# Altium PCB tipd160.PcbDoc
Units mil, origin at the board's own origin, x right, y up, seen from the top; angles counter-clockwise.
Board outline 4480.01 x 3875.01 mil, 4 copper layers (Top Layer, gnd, power, Bottom Layer), stack 90 mil thick; 78 components, 26 nets, 223 pads, 56 vias.
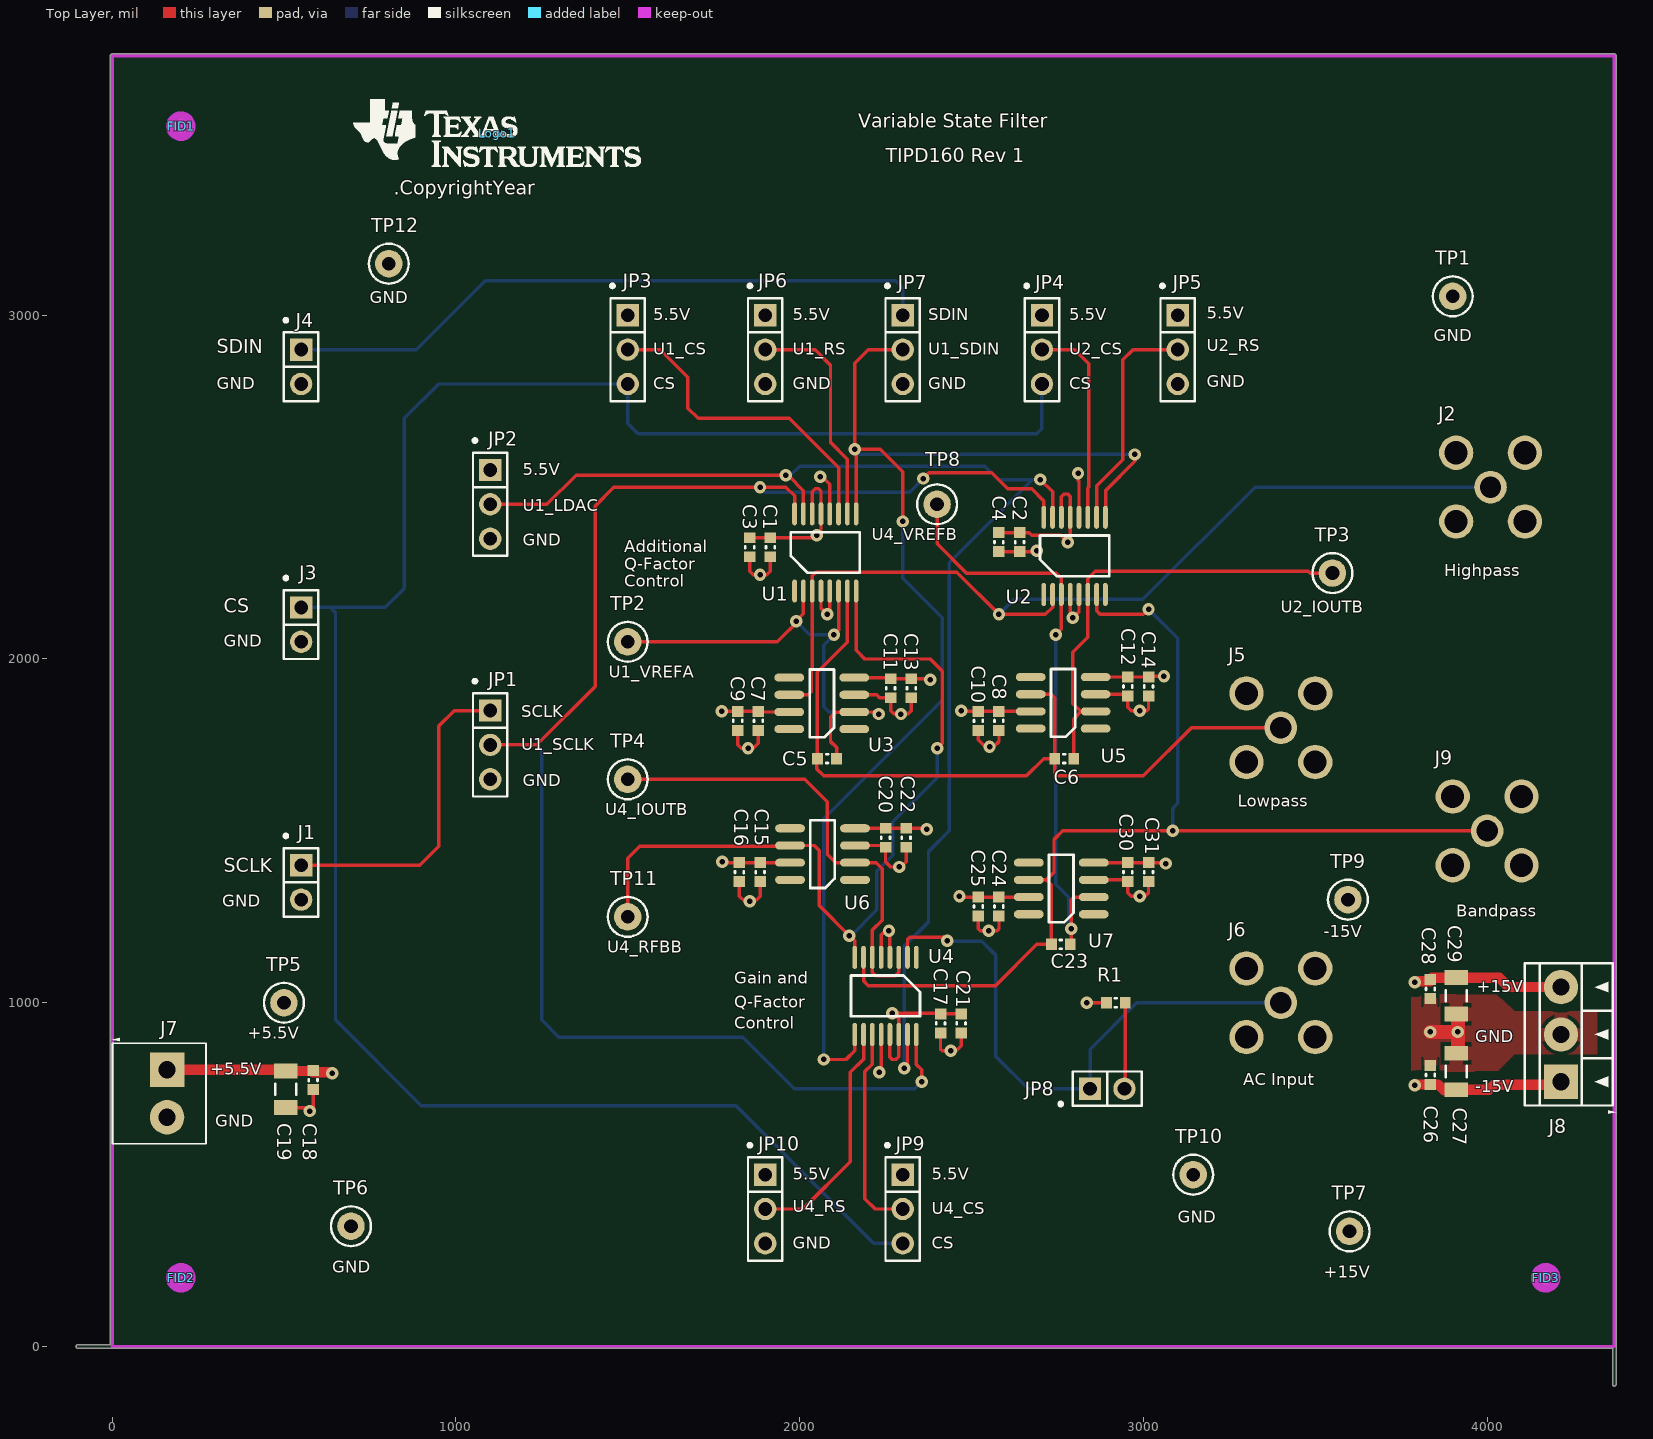
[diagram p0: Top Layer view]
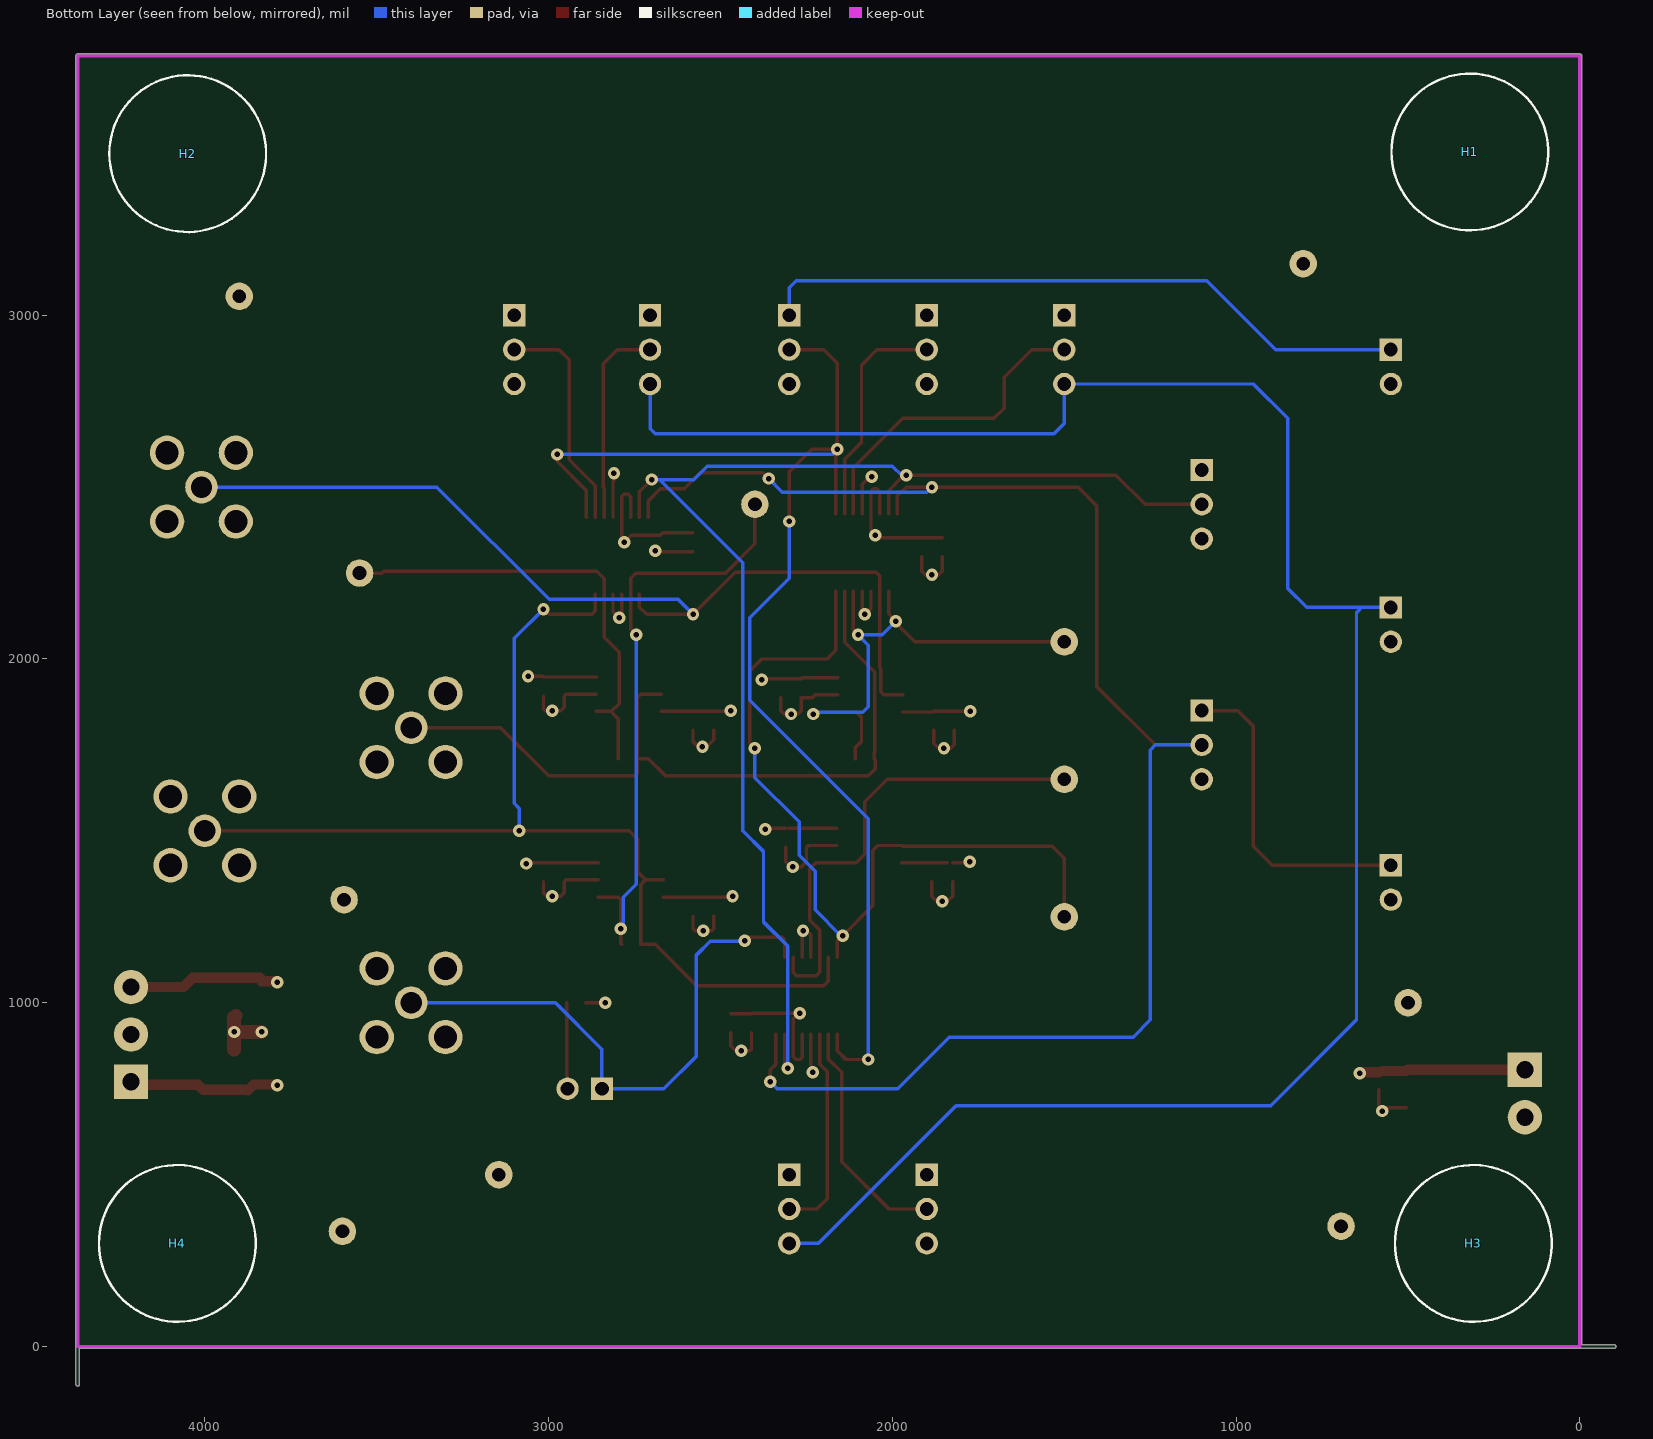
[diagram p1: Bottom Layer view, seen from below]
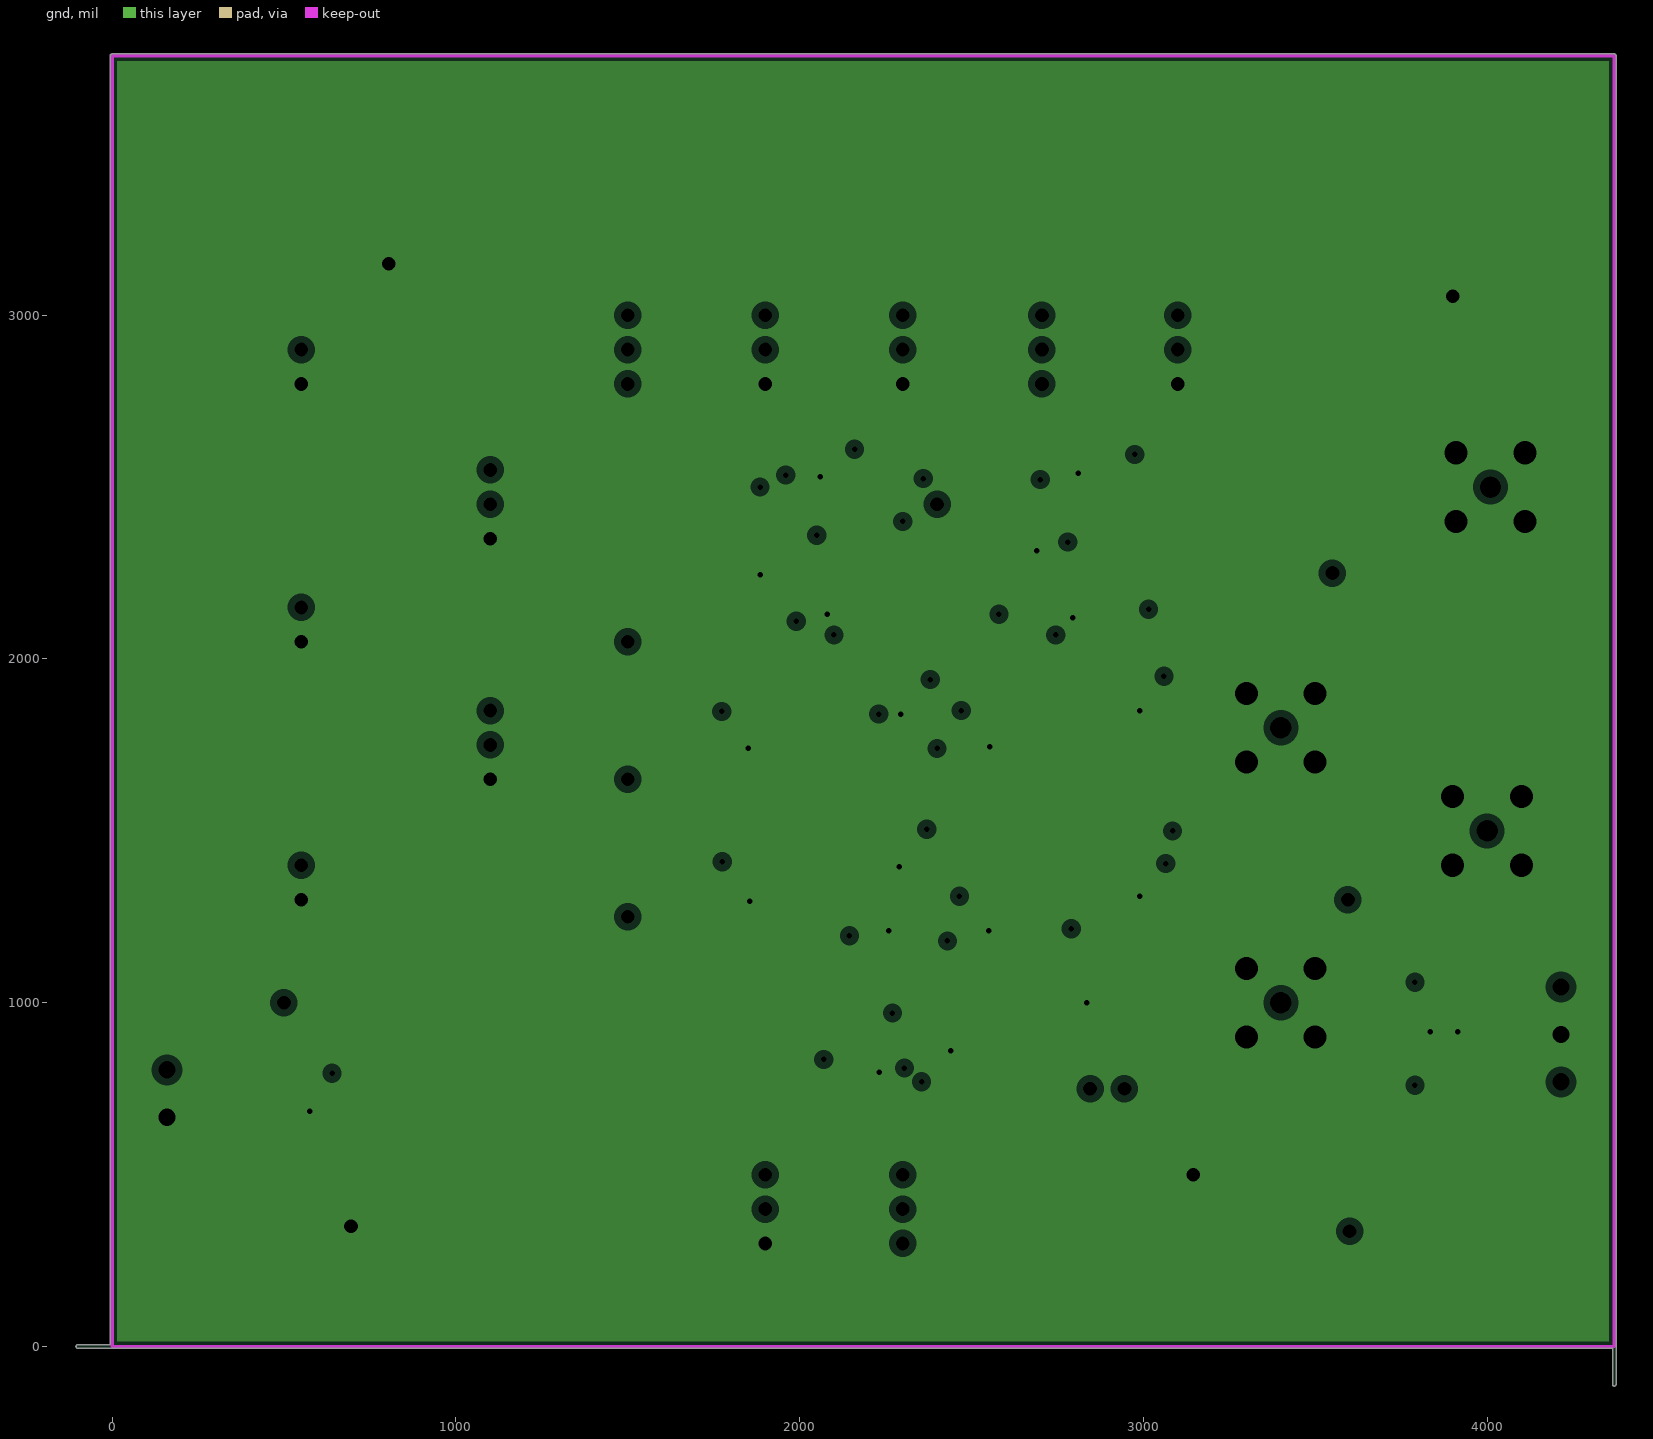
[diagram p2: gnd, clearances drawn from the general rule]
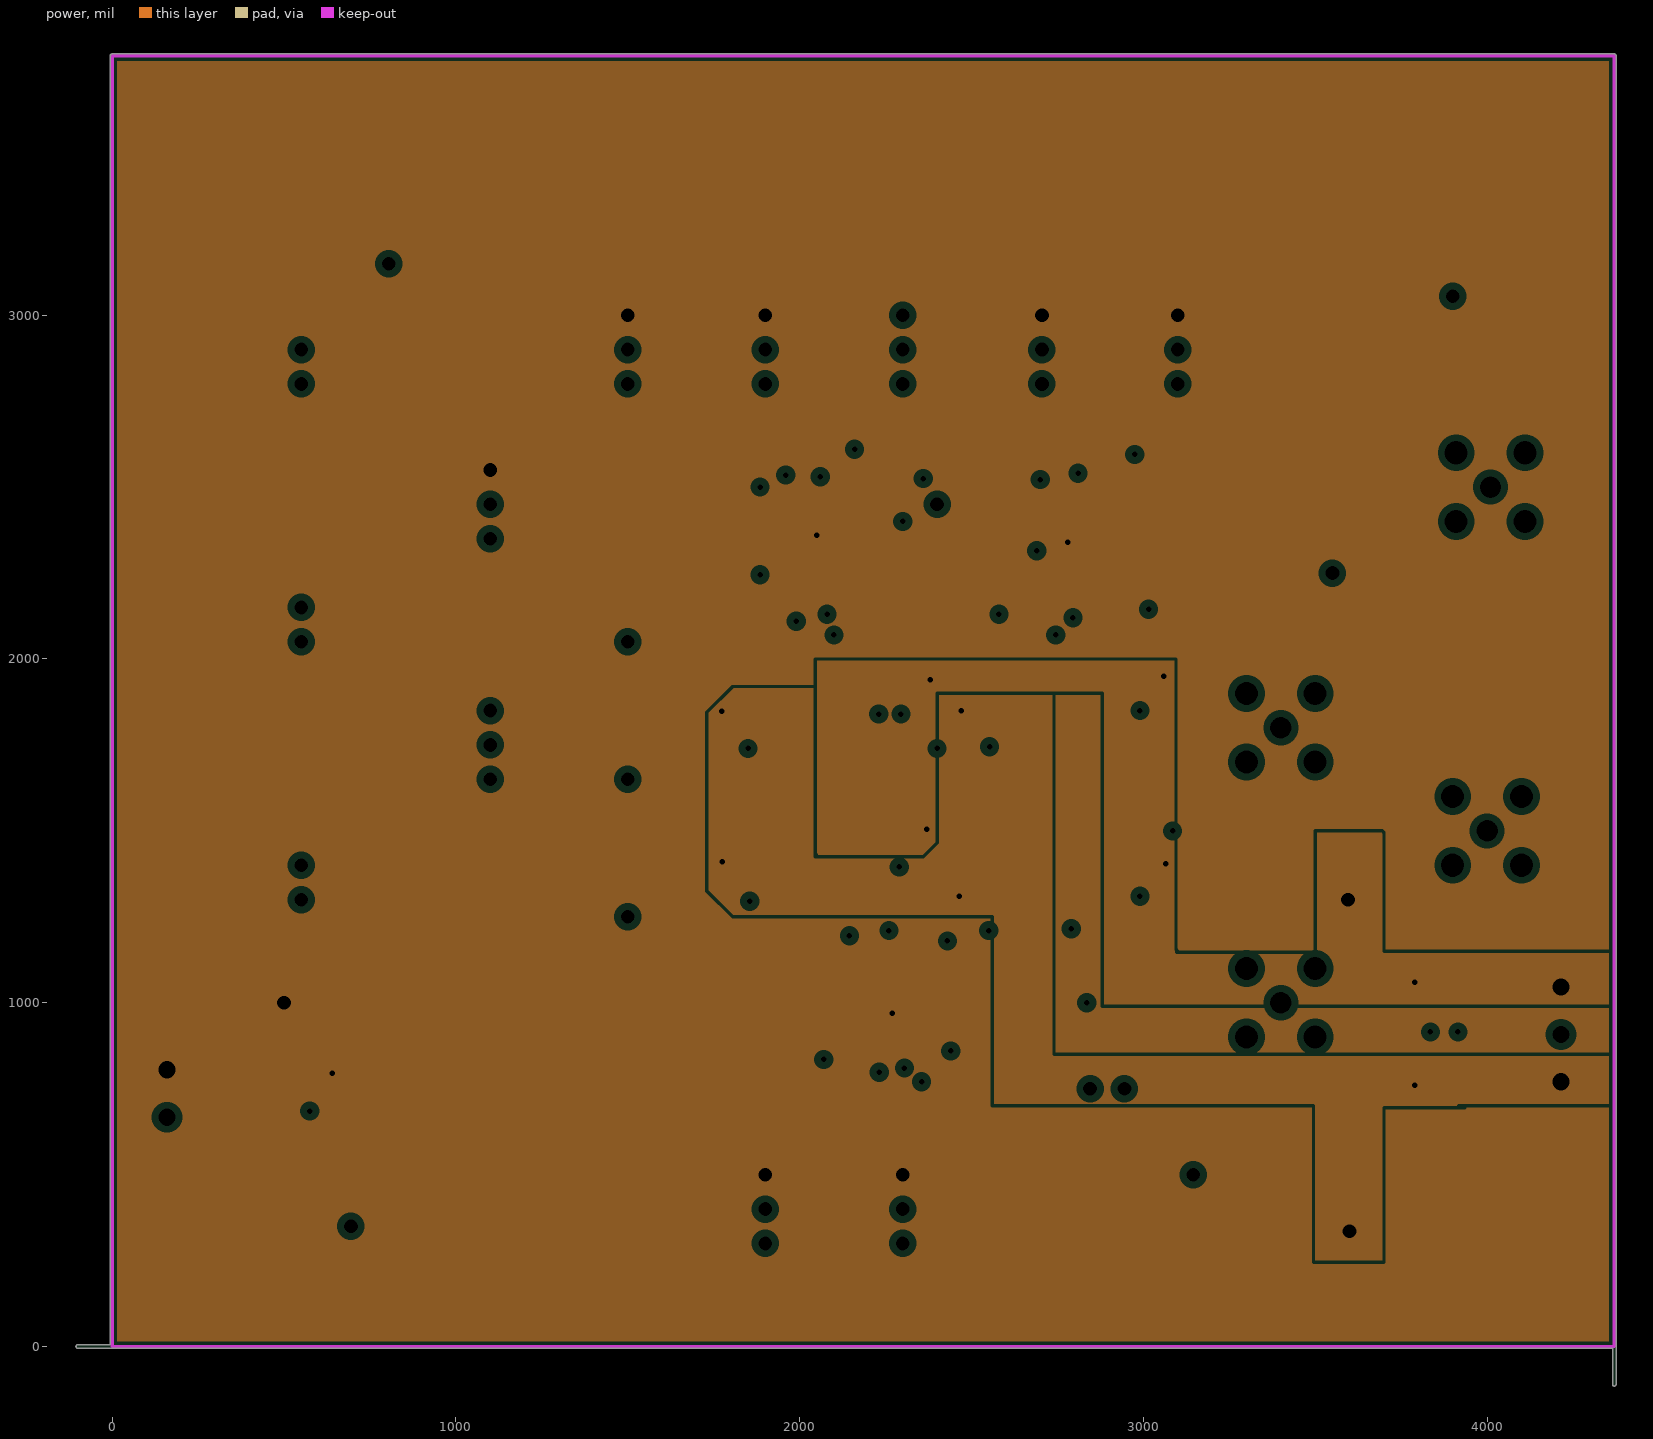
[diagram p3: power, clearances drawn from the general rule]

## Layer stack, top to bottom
Top Layer: signal copper 1.4
Dielectric: core 59.2, FR-4, Dk 4.8
gnd: plane copper 1.4, net GND
Dielectric: prepreg 12.6, FR-4, Dk 4.8
power: plane copper 1.4, net (Multiple Nets)
Dielectric: core 12.6, FR-4, Dk 4.8
Bottom Layer: signal copper 1.4

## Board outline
-100,-5.01 cw(c-100,0) -100,5.02 -5.01,5.02 -5.01,3755 cw(c0,3755) 0,3760.02 4370,3760.02 cw(c4370,3755) 4375.02,3755 4375.02,-110 cw(c4370,-110) 4364.98,-110 4364.98,-5.01

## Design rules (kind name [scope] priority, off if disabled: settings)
AcuteAngle [All] p1: minimum=4.50000000000000E+0001 checktracksonly=FALSE
AssemblyTestPointUsage [All] p1: valid=2
Clearance Clearance_BoardEdge_MountingHoles [OnCopper and InComponentClass('Mounting Holes') vs IsKeepOut] p1: gap=40
Clearance Clearance_BoardEdge_Poly [OnCopper and InPoly vs IsKeepOut] p2: gap=25
Clearance Clearance_BoardEdge [OnCopper and Not InComponentClass('Logo') and not InComponentClass('FiducialMark') and not InRegion(1000,500,4000,800) and Not IsKeepout vs IsKeepOut] p3: gap=75
Clearance Clearance_Poly [InPolygon] p4: gap=25
Clearance [All] p5: gap=8
ComponentClearance ComponentClearance_Shunt [InComponentClass('Header') vs InComponentClass('Shunt')] p1: gap=0 collisioncheckmode=3 verticalgap=0 showdistances=FALSE
ComponentClearance ComponentClearance_Logo [InComponentClass('Logo')] p2: gap=50 collisioncheckmode=3 verticalgap=10 showdistances=FALSE
ComponentClearance ComponentClearance_ScrewToNut [(HasFootprint('NY PMS 440 0025 PH')) vs (HasFootprint('Keystone_1902C'))] p3: gap=5 collisioncheckmode=3 verticalgap=10 showdistances=FALSE
ComponentClearance ComponentClearance_MountingHoles [InComponentClass('Mounting Holes')] p4: gap=250 collisioncheckmode=3 verticalgap=100000 showdistances=FALSE
ComponentClearance ComponentClearance_SmallPassives [HasFootprint('0201*') or HasFootprint('0402*') or HasFootprint('0508') or HasFootprint('0603*') or HasFootprint('0612') or HasFootprint('0805*') or HasFootprint('0815*') or HasFootprint('0830*') or HasFootprint('1206*') or HasFootprint('1210*') or HasFootprint('1808*') or HasFootprint('1812*') or HasFootprint('1825*') or HasFootprint('2010*') or HasFootprint('2220*') or HasFootprint('2225*') or HasFootprint('2512*') or HasFootprint('2728*') or HasFootprint('3518*') vs HasFootprint('0201*') or HasFootprint('0402*') or HasFootprint('0508') or HasFootprint('0603*') or HasFootprint('0612') or HasFootprint('0805*') or HasFootprint('0815*') or HasFootprint('0830*') or HasFootprint('1206*') or HasFootprint('1210*') or HasFootprint('1808*') or HasFootprint('1812*') or HasFootprint('1825*') or HasFootprint('2010*') or HasFootprint('2220*') or HasFootprint('2225*') or HasFootprint('2512*') or HasFootprint('2728*') or HasFootprint('3518*')] p5: gap=20 collisioncheckmode=3 verticalgap=10 showdistances=FALSE
ComponentClearance ComponentClearance_THtoSMT [IsThruComponent vs IsSMTComponent] p6: gap=100 collisioncheckmode=3 verticalgap=30 showdistances=FALSE
ComponentClearance ComponentClearance_THtoTH [IsThruComponent vs IsThruComponent] p7: gap=118.11 collisioncheckmode=3 verticalgap=30 showdistances=FALSE
ComponentClearance [All] p8: gap=40 collisioncheckmode=3 verticalgap=10 showdistances=FALSE
DiffPairsRouting [All] p1: maxlimit=100 minlimit=10 mostfreqgap=10 maxuncoupledlength=1000
FabricationTestPointUsage TestPointUsage [All] p1: valid=2 allowmultiple=FALSE
FabricationTestpoint Testpoint [All] p1: side=3 testpointundercomponent=TRUE minsize=40 maxsize=100 preferedsize=60 minholesize=0 maxholesize=40 preferedholesize=32 testpointgrid=1 allowsidetop=TRUE allowsidebottom=TRUE usegrid=TRUE gridtolerance=0.01
FanoutControl Fanout_LCC [IsLCC] p1: bgadir=Out bgaviamode=Centered fanoutstyle=Auto fanoutdirection=Alternating viagrid=1 // Fanout_LCC (Default Rule)
FanoutControl Fanout_BGA [IsBGA] p2: bgadir=Out bgaviamode=Centered fanoutstyle=Auto fanoutdirection=Alternating viagrid=1 // Fanout_BGA (Default Rule)
FanoutControl Fanout_Default [All] p4: bgadir=Out bgaviamode=Centered fanoutstyle=Auto fanoutdirection=Alternating viagrid=1 // Fanout_Default (Default Rule)
FanoutControl Fanout_Small [(CompPinCount < 5)] p5: bgadir=Out bgaviamode=Centered fanoutstyle=Auto fanoutdirection=OutThenIn viagrid=1 // Fanout_Small (Default Rule)
HoleSize [All] p1: absolutevalues=TRUE maxlimit=251 minlimit=8 maxpercent=80.000 minpercent=20.000
MinimumAnnularRing MinimumAnnularRing_ThermalPadVias [IsVia and InAnyComponent] p1: minimumring=5.91
MinimumAnnularRing [All] p2: minimumring=9
MinimumSolderMaskSliver MinimumSolderMaskSliver_Logo [InComponentClass('Logo') vs InComponentClass('Logo')] p1: minsoldermaskwidth=0.7
MinimumSolderMaskSliver [All] p2: minsoldermaskwidth=3.94
PlaneClearance [All] p1: clearance=20
PlaneConnect [All] p1: planeconnectstyle=Relief reliefexpansion=10 reliefentries=4 reliefconductorwidth=10 reliefairgap=10
PolygonConnect PolygonConnect_3 [All vs IsNamedPolygon('Top Layer-No Net')] p1: connectstyle=Relief reliefconductorwidth=40 reliefentries=4 polygonreliefangle="90 Angle" airgapwidth=10
PolygonConnect PolygonConnect_2 [(InNet('AGND') AND InPadClass('All Pads')) vs IsNamedPolygon('Top Layer-No Net')] p2: connectstyle=Relief reliefconductorwidth=10 reliefentries=4 polygonreliefangle="90 Angle" airgapwidth=10
PolygonConnect PolygonConnect_1 [All vs IsNamedPolygon('Top Layer-No Net')] p3: connectstyle=Relief reliefconductorwidth=40 reliefentries=4 polygonreliefangle="90 Angle" airgapwidth=10
PolygonConnect [All] p4: connectstyle=Relief reliefconductorwidth=10 reliefentries=4 polygonreliefangle="90 Angle" airgapwidth=10
RoutingVias ThermalPadVias [IsVia and InAnyComponent] p1: holewidth=7.87 width=19.68 viastyle="Through Hole" minholewidth=7.87 minwidth=19.68 maxholewidth=12.99 maxwidth=23.62
RoutingVias [All] p2: holewidth=16 width=34 viastyle="Through Hole" minholewidth=7.87 minwidth=26 maxholewidth=40 maxwidth=65
SMDToCorner [All] p1: distance=30000
SilkToSilkClearance [All] p1: silktosilkclearance=5
SilkscreenOverComponentPads [All] p1: minsilkscreentomaskgap=5
SolderMaskExpansion [All] p1: expansion=1.97
Width [All] p1: maxlimit=100 minlimit=6 preferedwidth=10 checkconnectedcopper=TRUE
13 further rules are at their usual default settings.

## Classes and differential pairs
component class Logo: Logo1
component class tipd160_hw: FID1 FID2 FID3 H1 H2 H3 H4 Logo1
component class FiducialMark: FID1 FID2 FID3
component class TIPD160: C1 C2 C3 C4 C5 C6 C7 C8 C9 C10 C11 C12 C13 C14 C16 C17 C19 C20 C21 C22 C23 C24 C25 C29 C30 C31 J1 J2 J3 J4 J5 J6 J7 J8 J9 JP1 JP2 JP3 JP4 JP5 JP6 JP7 JP8 JP9 JP10 R1 TP1 TP2 TP3 TP4 TP5 TP6 TP7 TP8 TP9 TP10 TP11 TP12 U1 U2 U3 U4 U5 U6 U7
component class Header: J1 J3 J4 JP1 JP2 JP3 JP4 JP5 JP6 JP7 JP8 JP9 JP10

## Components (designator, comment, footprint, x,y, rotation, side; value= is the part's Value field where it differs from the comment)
C1 "GRM188R61E104KA01D" 0603L 1915,2325 r270 top
C2 "GRM188R61E104KA01D" 0603L 2640,2340 r90 top
C3 "C1608C0G1H101J" 0603L 1855,2325 r270 top
C4 "C1608C0G1H101J" 0603L 2580,2340 r90 top
C5 "" 0603L 2080,1710 r180 top
C6 "GRM188R71H102KA01D" 0603L 2770,1710 r180 top
C7 "C1608C0G1H101J" 0603L 1880,1820 r90 top (schematic designator C15)
C8 "C1608C0G1H101J" 0603L 2580,1820 r270 top (schematic designator C18)
C9 "GRM188R61E104KA01D" 0603L 1820,1820 r90 top
C10 "GRM188R61E104KA01D" 0603L 2520,1820 r270 top
C11 "GRM188R61E104KA01D" 0603L 2265,1915 r90 top
C12 "GRM188R61E104KA01D" 0603L 2955,1920 r90 top
C13 "C1608C0G1H101J" 0603L 2325,1915 r90 top (schematic designator C26)
C14 "C1608C0G1H101J" 0603L 3015,1920 r90 top (schematic designator C27)
C15 "GRM188R61E104KA01D" 0603L 1885,1380 r90 top
C16 "C1608C0G1H101J" 0603L 1825,1380 r90 top (schematic designator C28)
C17 "GRM188R61E104KA01D" 0603L 2410,940 r90 top
C18 "GRM188R61E104KA01D" 0603L 585,775 r90 top
C19 "GRM31CR61E106KA12L" 1206L 505,748.15 r90 top
C20 "GRM188R61E104KA01D" 0603L 2250,1480 r90 top
C21 "C1608C0G1H101J" 0603L 2470,940 r90 top
C22 "C1608C0G1H101J" 0603L 2310,1480 r90 top
C23 "GRM188R71H102KA01D" 0603L 2760,1170 r0 top
C24 "C1608C0G1H101J" 0603L 2580,1280 r90 top
C25 "GRM188R61E104KA01D" 0603L 2520,1280 r90 top
C26 "GRM188R61E104KA01D" 0603L 3835,790 r270 top
C27 "GRM31CR61E106KA12L" 1206L 3910,800 r270 top
C28 "GRM188R61E104KA01D" 0603L 3835,1040 r270 top
C29 "GRM31CR61E106KA12L" 1206L 3910,1020 r270 top
C30 "GRM188R61E104KA01D" 0603L 2955,1380 r90 top
C31 "C1608C0G1H101J" 0603L 3015,1380 r90 top
FID1 "Fiducial" Fiducial10-20 200,3550 r0 top
FID2 "Fiducial" Fiducial10-20 200,200 r0 top
FID3 "Fiducial" Fiducial10-20 4170,200 r0 top
H1 "SJ-5303 (CLEAR)" Bumpon_SJ5003Transparent 320,3475 r270 bottom
H2 "SJ-5303 (CLEAR)" Bumpon_SJ5003Transparent 4050,3470 r180 bottom
H3 "SJ-5303 (CLEAR)" Bumpon_SJ5003Transparent 310,300 r180 bottom
H4 "SJ-5303 (CLEAR)" Bumpon_SJ5003Transparent 4080,300 r180 bottom
J1 "TSW-102-07-G-S" TSW-102-07-G-S 550,1350 r270 top
J2 "142-0701-201" Johnson_142-0701-20x 4010,2500 r0 top
J3 "TSW-102-07-G-S" TSW-102-07-G-S 550,2100 r270 top
J4 "TSW-102-07-G-S" TSW-102-07-G-S 550,2850 r270 top
J5 "142-0701-201" Johnson_142-0701-20x 3400,1800 r0 top
J6 "142-0701-201" Johnson_142-0701-20x 3400,1000 r0 top
J7 "ED555/2DS" TERM_BLK_ED555-2DS 160,805 r270 top
J8 "ED555/3DS" TERM_BLK_ED555-3DS 4215,770 r90 top
J9 "142-0701-201" Johnson_142-0701-20x 4000,1500 r0 top
JP1 "TSW-103-07-G-S" TSW-103-07-G-S 1100,1750 r270 top
JP2 "TSW-103-07-G-S" TSW-103-07-G-S 1100,2450 r270 top
JP3 "TSW-103-07-G-S" TSW-103-07-G-S 1500,2900 r270 top
JP4 "TSW-103-07-G-S" TSW-103-07-G-S 2705,2900 r270 top
JP5 "TSW-103-07-G-S" TSW-103-07-G-S 3100,2900 r270 top
JP6 "TSW-103-07-G-S" TSW-103-07-G-S 1900,2900 r270 top
JP7 "TSW-103-07-G-S" TSW-103-07-G-S 2300,2900 r270 top
JP8 "TSW-102-07-G-S" TSW-102-07-G-S 2895,750 r0 top
JP9 "TSW-103-07-G-S" TSW-103-07-G-S 2300,400 r270 top
JP10 "TSW-103-07-G-S" TSW-103-07-G-S 1900,400 r270 top
Logo1 "Texas Instruments" TI_Stacked_Overlay_Small 1120,3530 r0 top
R1 "RC0603FR-0749R9L" 0603L 2920,1000 r0 top
TP1 "5001" Keystone5001 3900,3055 r0 top
TP2 "5000" Keystone5000 1500,2050 r0 top
TP3 "5000" Keystone5000 3550,2250 r0 top
TP4 "5000" Keystone5000 1500,1650 r0 top
TP5 "5000" Keystone5000 500,1000 r90 top
TP6 "5001" Keystone5001 695,350 r0 top
TP7 "5000" Keystone5000 3600,335 r90 top
TP8 "5000" Keystone5000 2400,2450 r0 top
TP9 "5000" Keystone5000 3595,1300 r90 top
TP10 "5001" Keystone5001 3145,500 r0 top
TP11 "5000" Keystone5000 1500,1250 r0 top
TP12 "5001" Keystone5001 805,3150 r0 top
U1 "DAC8812ICPW" PW0016A_N 2075,2310 r90 top
U2 "DAC8812ICPW" PW0016A_N 2800,2300 r90 top
U3 "OPA277U" D0008A_N 2064.57,1870.87 r180 top
U4 "DAC8812ICPW" PW0016A_N 2250,1020 r270 top
U5 "OPA277U" D0008A_N 2766.69,1872.48 r180 top
U6 "OPA277U" D0008A_N 2066.69,1432.48 r180 top
U7 "OPA277U" D0008A_N 2761.26,1332.48 r180 top

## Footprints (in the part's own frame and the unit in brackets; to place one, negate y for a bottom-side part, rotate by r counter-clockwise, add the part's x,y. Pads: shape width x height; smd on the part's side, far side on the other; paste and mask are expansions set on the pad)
0603L [mm] "0603 from SM-752 data"
  rect 0.8x0.85 smd: 1(-0.7,0) 2(0.7,0)
  silkscreen extent -0.07,-0.33 0.07,0.33, body extent -0.87,-0.47 0.87,0.47, height 0.85
1206L [mm] "1206 from SM-752 data"
  rect 1.1x1.75 smd: 1(-1.35,0) 2(1.35,0)
  silkscreen extent -0.4,-0.77 0.4,0.77, body extent -1.7,-0.9 1.7,0.9, height 1.35
Bumpon_SJ5003Transparent [mil] "3M Hemispherical Bumpon transparent"
  round 1 on Mech4: 0(0,0)
  silkscreen extent -228,-228 228,228, body extent -217,-218 219,218, height 197
D0008A_N [mm] "SOIC, 8-Leads, Body 4.9x3.9mm, Pitch 1.27mm, IPC Medium Density"
  oval 2.2x0.6 smd: 1(-2.4,1.905) 2(-2.4,0.635) 3(-2.4,-0.635) 4(-2.4,-1.905) 5(2.4,-1.905) 6(2.4,-0.635) 7(2.4,0.635) 8(2.4,1.905)
  silkscreen extent -0.9,-2.5 0.9,2.5, body extent -3,-2.45 3,2.45, height 1.63
Fiducial10-20 [mm]
  round 1 smd paste-0.5 mask+0.5: 1(0,0)
  Top Layer keep-out circle w1.178: c0,0 r0.5
Johnson_142-0701-20x [mil] "Johnson Components recommended land pattern"
  round 95 hole 62: 1(0,0)
  round 100 hole 67: 2(100,100) 3(100,-100) 4(-100,-100) 5(-100,100)
  body extent -156,-156 156,156, height 375
Keystone5000 [mil] "For Keystone 500x miniature loop terminals"
  round 80 hole 40: 1(0,0)
  silkscreen extent -58,-58 58,58, body extent -49,-49 49,49, height 182
Keystone5001 [mil] "For Keystone 500x miniature loop terminals"
  round 80 hole 40: 1(0,0)
  silkscreen extent -58,-58 58,58, body extent -49,-49 49,49, height 182
PW0016A_N [mm] "TSOP, 16-Leads, Body 5x4.4mm, Pitch 0.65mm, IPC Medium Density"
  oval 1.7x0.35 smd: 1(-2.85,2.275) 2(-2.85,1.625) 3(-2.85,0.975) 4(-2.85,0.325) 5(-2.85,-0.325) 6(-2.85,-0.975) 7(-2.85,-1.625) 8(-2.85,-2.275) 9(2.85,-2.275) 10(2.85,-1.625) 11(2.85,-0.975) 12(2.85,-0.325) 13(2.85,0.325) 14(2.85,0.975) 15(2.85,1.625) 16(2.85,2.275)
  silkscreen extent -1.5,-2.55 1.5,2.55, body extent -3.21,-2.5 3.21,2.5, height 0.98
TERM_BLK_ED555-2DS [mil]
  rect 100x100 hole 50: 1(0,0)
  round 100 hole 50: 2(138,0)
  silkscreen extent -93,-161 215,113, body extent -69,-150 207,106, height 323
TERM_BLK_ED555-3DS [mm]
  rect 2.54x2.54 hole 1.27: 1(0,0)
  round 2.54 hole 1.27: 2(3.5,0) 3(7,0)
  silkscreen extent -2.36,-4.09 8.75,2.67, body extent -1.75,-3.83 8.75,2.67, height 8.2
TI_Stacked_Overlay_Small [mil]
  silkscreen extent -418,-98 418,98
TSW-102-07-G-S [mm] "Samtec 100mil, 1x2, 230 mil above insulator"
  rect 1.65x1.65 hole 1.016 mask+0: 1(-1.27,0)
  round 1.65 hole 1.016 mask+0: 2(1.27,0)
  silkscreen extent -3.56,-1.27 2.54,1.27, body extent -2.54,-1.27 2.54,1.27, height 8.38
TSW-103-07-G-S [mm] "Samtec 100mil, 1x3, 230 mil above insulator"
  rect 1.65x1.65 hole 1.016 mask+0: 1(-2.54,0)
  round 1.65 hole 1.016 mask+0: 2(0,0) 3(2.54,0)
  silkscreen extent -4.83,-1.27 3.81,1.27, body extent -3.81,-1.27 3.81,1.27, height 8.38

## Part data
C1 C2 C9 C10 C11 C12 C15 C17 C18 C20 C25 C26 C28 C30: "CAP, CERM, 0.1uF, 25V, +/-10%, X5R, 0603"
C3 C4 C7 C8 C13 C14 C16 C21 C22 C24 C31: "CAP, CERM, 100pF, 50V, +/-5%, C0G/NP0, 0603"
C5: library part GRM188R71H102KA01D, "Not Installed"
C6 C23: "CAP, CERM, 1000pF, 50V, +/-10%, X7R, 0603"
C19 C27 C29: "CAP, CERM, 10uF, 25V, +/-10%, X5R, 1206"
FID1 FID2 FID3: "Fiducial mark.  There is nothing to buy or mount."
H1 H2 H3 H4: "Bumpon, Hemisphere, 0.44 X 0.20, Clear"
J1 J3 J4 JP8: "Header, 100mil, 2x1, Gold, TH"
J2 J5 J6 J9: "Connector, TH, SMA"
J7: "Terminal Block, 6A, 3.5mm Pitch, 2-Pos, TH"
J8: "Terminal Block, 6A, 3.5mm Pitch, 3-Pos, TH"
JP1 JP2 JP3 JP4 JP5 JP6 JP7 JP9 JP10: "Header, TH, 100mil, 3x1, Gold plated, 230 mil above insulator"
Logo1: library part TI_Logo, "Texas Instrument Corporate Signature"
R1: "RES, 49.9 ohm, 1%, 0.1W, 0603"
TP1 TP6 TP10 TP12: "Test Point, Miniature, Black, TH"
TP2 TP3 TP4 TP5 TP7 TP8 TP9 TP11: "Test Point, Miniature, Red, TH"
U1 U2 U4: "Dual, Serial Input 16-Bit Multiplying Digital-to-Analog Converter, PW0016A"
U3 U5 U6 U7: "High Precision OPERATIONAL AMPLIFIER, D0008A"

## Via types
v1: diameter 36, hole 16, Top Layer to Bottom Layer, 56 vias

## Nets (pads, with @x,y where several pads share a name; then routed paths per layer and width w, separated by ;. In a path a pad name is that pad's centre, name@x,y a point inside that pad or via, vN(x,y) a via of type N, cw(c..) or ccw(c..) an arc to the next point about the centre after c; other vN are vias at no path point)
+5.5V: C1.1 C2.2 C3.1 C4.2 C17.2 C18.2 C19.2 C21.2 J7.1 JP2.1 JP3.1 JP4.1 JP5.1 JP6.1 JP9.1 JP10.1 TP5.1 U1.13 U1.14 U2.13 U2.14 U4.13 U4.14 | length 1752.1
  Top Layer w10: C3.1 C1.1 2042.56,2352.56 v1(2050,2360) 2062.21,2372.21 U1.13 2062.21,2487.79 2055,2495 2045,2495 2036.62,2486.62 U1.14 ; U4.13 2262.8,842.2 2270,835 2280,835 2288.39,843.39 U4.14 2288.39,953.39 v1@2275,966.77 ; v1(2270,970) 2407.56,970 C17.2 C21.2 ; C4.2 C2.2 2667.44,2367.56 2675,2360 2760,2360 v1(2780,2340) 2787.2,2347.2 U2.13 2787.2,2472.8 2780,2480 2770,2480 2761.61,2471.61 U2.14
  Top Layer w30: J7.1 501.3,805 C19.2 C18.2@574.41,801.3 ; C18.2@585,797.56 v1@627.56,797.56
  other v1: 640,795
+15V: C7.2 C8.1 C9.2 C10.1 C15.2 C16.2 C24.2 C25.2 C26.2 C27.2 J8.1 TP7.1 U3.7 U5.7 U6.7 U7.7 | length 1224.3
  Top Layer w10: v1(1773.72,1847.56) C9.2 C7.2 ; v1(1775,1410) 1775,1405 1777.56,1407.56 C16.2 ; C16.2@1840,1407.56 1889.92,1407.56 1890,1407.48 U6.7 ; C7.2@1880,1845.87 U3.7 ; v1(2465,1310) 2467.44,1307.56 C25.2 2589.92,1307.56 2590,1307.48 U7.7 ; v1@2480,1850 2482.44,1847.56 C10.1 C8.1 ; C8.1@2580,1847.48 U5.7
  Top Layer w30: v1(3790,760) 3792.44,762.44 C26.2 3857.13,762.44 3874.57,745 3876.42,746.85 C27.2 4005,746.85 4020,761.85 4206.85,761.85 J8.1
  other v1: 2470,1850
-15V: C11.2 C12.2 C13.2 C14.2 C20.2 C22.2 C28.1 C29.1 C30.2 C31.2 J8.3 TP9.1 U3.4 U5.4 U6.4 U7.4 | length 1264.8
  Top Layer w10: U3.4 2261.69,1945.87 C11.2 C13.2 v1@2367.56,1942.56 ; U6.4 2239.92,1507.48 2240,1507.56 C20.2 C22.2@2300,1507.56 ; C22.2 2367.44,1507.56 v1(2370,1505) ; U7.4 C30.2@2955,1407.48 ; U5.4 2861.26,1947.56 C12.2 C14.2 3017.44,1950 v1(3060,1950) v1@3065,1950 ; C30.2 C31.2 3062.44,1407.56 v1(3065,1405)
  Top Layer w30: v1(3790,1060) 3792.56,1062.56 C28.1@3835,1062.56 ; C28.1 3840.59,1073.15 C29.1 4035,1073.15 4062.56,1045.59 J8.3
  other v1: 2380,1940
/LDAC: JP2.2 U1.15 U2.15 U4.15 | length 3872
  Top Layer w10: JP2.2 1265,2450 1350,2535 v1(1960,2535) ; v1@1970,2531.02 2011.02,2490 U1.15 ; v1(2305,810) 2313.98,818.98 U4.15 ; v1(2700,2522.05) 2736.02,2486.02 U2.15
  Bottom Layer w10: v1@1970,2531.02 1999.98,2561 2539,2561 2577.95,2522.05 2677.05,2522.05 ; v1(2305,810) 2305,1165 2375,1235 2375,1440 2435,1500 2435,2280 2677.05,2522.05 ; v1(2700,2522.05) 2677.05,2522.05
CS: J3.1 JP3.3 JP4.3 JP9.3 | length 6103.3
  Bottom Layer w10: J3.1 635,2150 ; JP9.3 2215,300 1815,700 900,700 650,950 650,2135 635,2150 ; JP4.3 2705,2670 2690,2655 1530,2655 1500,2685 JP3.3 950,2800 850,2700 850,2205 795,2150 635,2150
GND: C1.2 C2.1 C3.2 C4.1 C7.1 C8.2 C9.1 C10.2 C11.1 C12.1 C13.1 C14.1 C15.1 C16.1 C17.1 C18.1 C19.1 C20.1 C21.1 C22.1 C24.1 C25.1 C26.1 C27.1 C28.2 C29.2 C30.1 C31.1 J1.2 J2.2 J2.3 J2.4 J2.5 J3.2 J4.2 J5.2 J5.3 J5.4 J5.5 J6.2 J6.3 J6.4 J6.5 J7.2 J8.2 J9.2 J9.3 J9.4 J9.5 JP1.3 JP2.3 JP5.3 JP6.3 JP7.3 JP10.3 R1.1 TP1.1 TP6.1 TP10.1 TP12.1 U1.4 U1.5 U1.12 U2.4 U2.5 U2.12 U3.3 U4.4 U4.5 U4.12 U5.3 U6.3 U7.3 | length 3160.2
  Top Layer w10: C19.1 565,695 v1(575,685) 585,695 C18.1 ; C9.1 1820,1750 1830,1740 v1(1850,1740) 1865,1740 1880,1755 C7.1 ; C16.1 1825,1310 1840,1295 v1(1855,1295) 1860,1300 1875,1300 1885,1310 C15.1 ; C3.2 1855,2255 1865,2245 v1(1885,2245) 1905,2245 1915,2255 C1.2 ; v1(2060,2530) 2065.59,2530 2087.8,2507.8 U1.12 ; U1.4 2062.21,2147.79 v1(2080,2130) 2087.8,2137.8 U1.5 ; U3.3 2224.13,1895.87 2232.56,1887.44 C11.1 2265,1850 2275,1840 v1(2295,1840) 2315,1840 2325,1850 C13.1 ; U6.3 2244.96,1457.48 C20.1 2250,1410 2265,1395 v1(2290,1395) 2295,1395 2310,1410 C22.1 ; v1(2231.8,797.96) 2237.2,803.36 U4.12 ; U4.5 2237.2,1197.2 2250,1210 v1(2260,1210) 2262.8,1207.2 U4.4 ; C17.1 2410,865 2415,860 v1(2440,860) 2455,860 2470,875 C21.1 ; C25.1 2520,1215 2525,1210 v1(2550,1210) 2575,1210 2580,1215 C24.1 ; C10.2 2520,1765 v1@2540,1745 ; v1(2552.5,1745) 2565,1745 2580,1760 C8.2 ; C4.1 C2.1 2687.44,2312.44 v1(2690,2315) ; U2.4 2787.2,2127.8 v1(2795,2120) 2812.8,2137.8 U2.5 ; v1(2810,2540) 2810,2520 2812.8,2517.2 U2.12 ; v1(2835,1000) R1.1 ; U7.3 2949.96,1357.48 C30.1 2955,1320 2965,1310 v1(2990,1310) 3005,1310 3015,1320 C31.1 ; U5.3 2949.96,1897.48 C12.1 2955,1860 2965,1850 v1(2990,1850) 3010,1850 3015,1855 C14.1
  Top Layer w40: v1(3835,915) v1(3915,915) ; C29.2@3910,961.85 3915,956.85 v1(3915,915) ; C27.1@3915,863.15 v1(3915,915)
NetC5_1: C5.1 TP2.1 U1.2 U1.6 U3.2 | length 1549.5
  Top Layer w10: TP2.1 1935,2050 v1@2000,2115 ; v1(1990,2110) 2011.02,2131.02 U1.2 ; v1(2100,2070) 2113.39,2083.39 U1.6 ; C5.1 2107.56,1742.44 2090,1760 2090,1830 2104.91,1844.91 2158.1,1844.91 U3.2 2224.13,1845.87 v1(2230,1840)
  Bottom Layer w10: v1(1990,2110) 2030,2070 v1(2100,2070) 2070,2040 2070,1861.33 2086.42,1844.91 2225.09,1844.91 v1(2230,1840)
NetC5_2: C5.2 C6.2 J5.1 U1.7 U5.6 | length 2289.8
  Top Layer w10: U1.7 2138.98,2048.98 2051.65,1961.65 2051.65,1728.35 2052.44,1727.56 C5.2 2050,1707.56 2050,1680 2070,1660 2660,1660 2710,1710 C6.2 ; U5.6 2732.52,1897.48 2742.44,1887.56 C6.2 ; J5.1 3140,1800 3000,1660 2750,1660 2742.44,1667.56 C6.2
NetC6_1: C6.1 TP3.1 U2.6 U5.2 | length 1326.1
  Top Layer w10: C6.1 2797.56,1825.43 U5.2@2819.61,1847.48 ; U5.2 U5.2@2819.61,1847.48 ; TP3.1 3485,2250 3480,2255 2860,2255 2838.39,2233.39 U2.6 2838.39,2063.39 2795,2020 2795,1870 2817.52,1847.48 U5.2@2819.61,1847.48
NetJ1_1: J1.1 JP1.1 | length 941.4
  Top Layer w10: J1.1 895,1400 950,1455 950,1805 995,1850 JP1.1
NetJ2_1: J2.1 U1.3 U2.2 U3.6 | length 2789.1
  Top Layer w10: U3.6 2025,1895.87 2033.65,1904.52 2033.65,1972.07 2036.62,1975.03 U1.3 2036.62,2241.62 2047.76,2252.76 2457.24,2252.76 v1(2580,2130) 2715,2130 2736.02,2151.02 U2.2
  Bottom Layer w10: v1(2580,2130) 2623.62,2173.62 2998.62,2173.62 3325,2500 J2.1
NetJ4_1: J4.1 JP7.1 | length 1921.1
  Bottom Layer w10: J4.1 885,2900 1085,3100 2280,3100 2300,3080 JP7.1
NetJ6_1: J6.1 JP8.1 U4.2 | length 1665.7
  Top Layer w10: U4.2 2313.98,1183.98 2320,1190 2420,1190 v1(2430,1180)
  Bottom Layer w10: v1(2430,1180) 2431,1179 2530,1179 2570,1139 2570,845 2665,750 JP8.1 2845,865 2980,1000 J6.1
NetJP3_2: JP3.2 U1.11 | length 942.8
  Top Layer w10: JP3.2 1595,2900 1675,2820 1675,2730 1705,2700 1970,2700 2113.39,2556.61 U1.11
NetJP4_2: JP4.2 U2.11 | length 600.9
  Top Layer w10: JP4.2 2800,2900 2841,2859 2841,2500 2838.39,2497.39 U2.11
NetJP5_2: JP5.2 U2.10 | length 661.7
  Top Layer w10: U2.10 2863.98,2503.98 2940,2580 2940,2870 2970,2900 JP5.2
NetJP6_2: JP6.2 U1.10 | length 661.7
  Top Layer w10: JP6.2 2045,2900 2090,2855 2090,2630 2138.98,2581.02 U1.10
NetJP8_2: JP8.2 R1.2 | length 251.1
  Top Layer w10: JP8.2 2947.56,752.56 R1.2
NetJP9_2: JP9.2 U4.11 | length 609.2
  Top Layer w10: U4.11 2211.61,821.61 2190,800 2190,430 2220,400 JP9.2
NetJP10_2: JP10.2 U4.10 | length 690.7
  Top Layer w10: JP10.2 2010,400 2147.5,537.5 2147.5,797.5 2186.02,836.02 U4.10
NetTP4_1: TP4.1 U4.3 U4.6 U6.2 | length 1378.9
  Top Layer w10: TP4.1 2015,1650 2080,1585 2080,1432.13 2104.64,1407.48 U6.2 2222.52,1407.48 2240,1390 2240,1240 2211.61,1211.61 U4.6 2211.61,1088.39 2220.94,1079.06 2279.06,1079.06 2288.39,1088.39 U4.3
NetTP11_1: TP11.1 U1.8 U4.8 U6.6 | length 2434.8
  Top Layer w10: TP11.1 1500,1420 1535,1455 1969.72,1455 U6.6 2042.52,1457.48 2057.02,1442.98 2057.02,1282.98 v1(2145,1195) 2160,1180 2160,1132.64 U4.8 ; U1.8 2164.57,2025.43 2190,2000 2380,2000 2415,1965 2415,1755 v1(2400,1740)
  Bottom Layer w10: v1(2145,1195) 2150,1195 2225,1270 2225,1383 2271,1429 2271,1526 2400,1655 v1(2400,1740)
SCLK: JP1.2 U1.16 U2.16 U4.16 | length 4789.4
  Top Layer w10: JP1.2 1235,1750 1405,1920 1405,2445 1460,2500 v1(1885,2500) 1960,2500 1985.43,2474.57 U1.16 ; U4.16 2339.57,820.43 2355,805 v1(2355,770) v1@2355,765 ; v1(2360,2525) 2376.52,2541.52 2558.48,2541.52 2605,2495 2675,2495 2710.43,2459.57 U2.16
  Bottom Layer w10: JP1.2 1235,1750 1250,1735 1250,950 1300,900 1835,900 1985,750 2335,750 v1(2355,770) ; v1(1885,2500) 1900,2485 2320,2485 v1(2360,2525)
SDIN: JP7.2 U1.9 U2.9 U4.9 | length 3851.4
  Top Layer w10: v1(2070,835) 2135,835 2160.43,860.43 U4.9 ; U1.9 2164.57,2605.43 v1(2160,2610) ; v1(2300,2400) 2300,2545 2235,2610 v1(2160,2610) ; JP7.2 2200,2900 2160,2860 v1(2160,2610) ; U2.9 2890,2412.64 2890,2490 2975,2575 v1(2975,2595)
  Bottom Layer w10: v1(2070,835) 2070,1535 2415,1880 2415,2120 2300,2235 v1(2300,2400) ; v1(2160,2610) 2175,2595 v1(2975,2595)
U4_7: C23.1 J9.1 U2.7 U4.7 U7.6 | length 3207.5
  Top Layer w10: U4.7 2186.02,1063.98 2200,1050 2570,1050 2690,1170 C23.1 2732.44,1343.39 2718.35,1357.48 ; U7.6 2718.35,1357.48 ; U2.7 2863.98,2140 2873.98,2130 3000,2130 v1(3015,2145) ; J9.1 2765,1500 2740,1475 2740,1379.14 2718.35,1357.48
  Bottom Layer w10: v1(3015,2145) 3100,2060 3100,1580 3085,1565 v1(3085,1500)
U6_2: C23.2 TP8.1 U2.3 U7.2 | length 1763.1
  Top Layer w10: TP8.1 2400,2335.46 2485.46,2250 2746.61,2250 2761.61,2235 U2.3 2761.61,2086.61 v1(2745,2070) ; C23.2 2790,1172.44 v1(2790,1215) 2790,1300 2797.48,1307.48 U7.2
  Bottom Layer w10: v1(2745,2070) 2745,1344.63 2783.11,1306.52 2783.11,1221.89 v1(2790,1215)
pads on no net: FID1.1 FID2.1 FID3.1 H1.0 H2.0 H3.0 H4.0 U1.1 U2.1 U2.8 U3.1 U3.5 U3.8 U4.1 U5.1 U5.5 U5.8 U6.1 U6.5 U6.8 U7.1 U7.5 U7.8

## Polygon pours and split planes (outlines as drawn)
GND on Top Layer "Top Layer-No Net" (solid, remove dead copper, pour order 2): 3780,1025 3780,800 4030,800 4080,850 4320,850 4320,976.51 4320.18,976.69 4318.49,975 4080,975 4030,1025
GND on gnd (split plane): 4354.92,15.08 15.08,15.08 15.08,3739.92 4354.92,3739.92
-15V on power (split plane): 3089.9,1155 3090.29,1153.05 3091.4,1151.4 3092.79,1150 3091.69,1148.35 3091.3,1146.4 3091.69,1144.44 3092.79,1142.79 3094.44,1141.69 3096.4,1141.3 3498.6,1141.3 3500.56,1141.69 3502.21,1142.79 3503.6,1144.19 3504.71,1145.84 3505.1,1147.79 3505.1,1494.9 3692.89,1494.9 3694.9,1492.89 3694.9,1150 3695.29,1148.05 3696.4,1146.4 3698.05,1145.29 3700,1144.9 4354.92,1144.9 4354.92,995.1 2885.1,995.1 2885.1,1899.92 2884.71,1901.87 2883.6,1903.53 2881.95,1904.63 2880,1905.02 2740.4,1905.02 2740,1905.1 2739.6,1905.02 2400.4,1905.02 2400,1905.1 2398.05,1904.71 2396.4,1903.6 2395.29,1901.95 2394.9,1900 2394.9,1899.92 2394.9,1809.49 2394.9,1467.11 2357.89,1430.1 2053.65,1430.1 2053.88,1431.22 2053.49,1433.17 2052.38,1434.83 2050.1,1437.11 2050.1,1920 2050.1,1994.9 3089.9,1994.9
+15V on power (split plane): 2874.9,990 2875.29,988.05 2876.4,986.4 2878.05,985.29 2880,984.9 4354.92,984.9 4354.92,855.1 2745.1,855.1 2745.1,1894.82 2874.9,1894.82
+15V on power (split plane): 2039.9,1435 2039.9,1425 2040.29,1423.05 2041.4,1421.4 2043.05,1420.29 2045,1419.9 2360,1419.9 2361.95,1420.29 2363.6,1421.4 2403.6,1461.4 2404.71,1463.05 2405.1,1465 2405.1,1894.82 2734.9,1894.82 2734.9,855 2734.9,850 2735.29,848.05 2736.4,846.4 2738.05,845.29 2740,844.9 4354.92,844.9 4354.92,705.1 3917.5,705.1 3915.55,704.71 3913.9,703.6 3912.79,701.95 3912.42,700.1 3700,700.1 3698.05,699.71 3696.4,698.6 3695.29,696.95 3694.9,695 3694.9,250.1 3500.1,250.1 3500.1,700 3499.71,701.95 3498.6,703.6 3496.95,704.71 3495,705.1 2565.1,705.1 2565.1,1250 2564.71,1251.95 2563.6,1253.6 2561.95,1254.71 2560,1255.1 1807.11,1255.1 1735.1,1327.11 1735.1,1842.89 1807.11,1914.9 2039.9,1914.9
+5.5V on power (split plane): 4354.92,1155.1 3705.1,1155.1 3705.1,1495 3704.71,1496.95 3703.6,1498.6 3698.6,1503.6 3696.95,1504.71 3695,1505.1 3500,1505.1 3498.05,1504.71 3496.4,1503.6 3495.29,1501.95 3494.9,1500 3494.9,1151.49 3104.8,1151.49 3104.71,1151.95 3103.6,1153.6 3100.1,1157.11 3100.1,2000 3099.71,2001.95 3098.6,2003.6 3096.95,2004.71 3095,2005.1 2045,2005.1 2043.05,2004.71 2041.4,2003.6 2040.29,2001.95 2039.9,2000 2039.9,1925.1 1805,1925.1 1803.05,1924.71 1801.4,1923.6 1726.4,1848.6 1725.29,1846.95 1724.9,1845 1724.9,1325 1725.29,1323.05 1726.4,1321.4 1801.4,1246.4 1803.05,1245.29 1805,1244.9 2554.9,1244.9 2554.9,700 2555.29,698.05 2556.4,696.4 2558.05,695.29 2560,694.9 3489.9,694.9 3489.9,245 3490.29,243.05 3491.4,241.4 3493.05,240.29 3495,239.9 3700,239.9 3701.95,240.29 3703.6,241.4 3704.71,243.05 3705.1,245 3705.1,689.9 3935,689.9 3936.95,690.29 3938.6,691.4 3939.71,693.05 3940.08,694.9 4354.92,694.9 4354.92,15.08 15.08,15.08 15.08,3739.92 4354.92,3739.92

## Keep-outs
Keep-Out Layer:
  lines w10: 0,0 0,3755 4370,3755 4370,0 0,0
  text ".Layer_Name" at 347,-1693.49 h40

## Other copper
Top Layer:
  text ".Layer_Name" at 347,-1693.49 h40
Bottom Layer:
  text ".Layer_Name" at 347,-1693.49 h40
power (plane layer: these items are gaps in the copper):
  lines w10: 2048.78,1431.22 2045,1435 2045,2000 3095,2000 3095,1155 3100,1150 ; 2400,1809.49 2400,1899.92 2880,1899.92 2880,990 4375.02,990 ; 2400,1900 2400,1465 2360,1425 2045,1425 2045,1920 1805,1920 1730,1845 1730,1325 1805,1250 2560,1250 2560,700 3012.5,700 3495,700 3495,245 3700,245 3700,695 3935,695 ; 2740,1900 2740,855 2740,850 4375.02,850 ; 3096.4,1146.4 3498.6,1146.4 3500,1147.79 3500,1500 3695,1500 3700,1495 3700,1150 4375.02,1150 ; 3917.5,700 4370,700

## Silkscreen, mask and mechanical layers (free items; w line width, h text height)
Top Overlay:
  text "Variable State Filter" at 2170,3545 h40
  text "TIPD160 Rev 1" at 2250,3445 h40
  text ".CopyrightYear" at 820,3350 h40
  text "GND" at 750,3035 h35
  text "5.5V" at 3185,2990 h35
  text "5.5V" at 1575,2985 h35
  text "5.5V" at 1980,2985 h35
  text "SDIN" at 2375,2985 h35
  text "5.5V" at 2785,2985 h35
  text "GND" at 3845,2925 h35
  text "U2_RS" at 3185,2895 h35
  text "SDIN" at 305,2890 h40
  text "U1_CS" at 1575,2885 h35
  text "U1_RS" at 1980,2885 h35
  text "U1_SDIN" at 2375,2885 h35
  text "U2_CS" at 2785,2885 h35
  text "GND" at 3185,2790 h35
  text "GND" at 305,2785 h35
  text "CS" at 1575,2785 h35
  text "GND" at 1980,2785 h35
  text "GND" at 2375,2785 h35
  text "CS" at 2785,2785 h35
  text "5.5V" at 1195,2535 h35
  text "U1_LDAC" at 1195,2430 h35
  text "U4_VREFB" at 2210,2345 h35
  text "GND" at 1195,2330 h35
  text "Additional" at 1490,2310 h35
  text "Q-Factor" at 1490,2260 h35
  text "Highpass" at 3875,2240 h35
  text "Control" at 1490,2210 h35
  text "CS" at 325,2135 h40
  text "U2_IOUTB" at 3400,2135 h35
  text "GND" at 325,2035 h35
  text "U1_VREFA" at 1445,1945 h35
  text "SCLK" at 1190,1830 h35
  text "U1_SCLK" at 1190,1735 h35
  text "GND" at 1195,1630 h35
  text "Lowpass" at 3275,1570 h35
  text "U4_IOUTB" at 1435,1545 h35
  text "SCLK" at 325,1380 h40
  text "GND" at 320,1280 h35
  text "Bandpass" at 3910,1250 h35
  text "-15V" at 3525,1190 h35
  text "U4_RFBB" at 1440,1145 h35
  text "Gain and" at 1810,1055 h35
  text "+15V" at 3970,1030 h35
  text "Q-Factor" at 1810,985 h35
  text "Control" at 1810,925 h35
  text "+5.5V" at 395,895 h35
  text "GND" at 3965,885 h35
  text "+5.5V" at 285,790 h35
  text "AC Input" at 3290,760 h35
  text "-15V" at 3965,740 h35
  text "GND" at 300,640 h35
  text "5.5V" at 1980,485 h35
  text "5.5V" at 2385,485 h35
  text "U4_RS" at 1980,390 h35
  text "U4_CS" at 2385,385 h35
  text "GND" at 3100,360 h35
  text "GND" at 1980,285 h35
  text "CS" at 2385,285 h35
  text "GND" at 640,215 h35
  text "+15V" at 3525,200 h35
  text ".Layer_Name" at 347,-1693.49 h40
Bottom Overlay:
  text ".Layer_Name" at 347,-1693.49 h40
Top Paste:
  text ".Layer_Name" at 347,-1693.49 h40
Bottom Paste:
  text ".Layer_Name" at 347,-1693.49 h40
Top Solder:
  text ".Layer_Name" at 347,-1693.49 h40
  text ".Layer_Name" at 347,-1693.49 h40
Bottom Solder:
  text ".Layer_Name" at 347,-1693.49 h40
Drill Guide:
  text ".Layer_Name" at 347,-1693.49 h40
M1 Board Outline:
  lines w10: 0,3755 0,0 4370,0 4370,3755 5,3755
  text ".Layer_Name" at 347,-1693.49 h40
M2 Board Dimensions:
  rectangle: -230.5,-1120.5 -105.5,-995.5
  rectangle: -105.5,-1245.5 269.5,-1120.5
  lines w7: -230.5,-1120.5 769.5,-1120.5 ; -105.5,-1245.5 -105.5,-995.5 ; 19.5,-1245.5 19.5,-995.5 ; 269.5,-1245.5 269.5,-995.5 ; 519.5,-1245.5 519.5,-995.5 ; -230.5,-1245.5 769.5,-1245.5 769.5,-995.5 -230.5,-995.5 -230.5,-1245.5
  lines w10: -230.5,-1310.5 -230.5,-1290.5 ; -170.5,-1320.5 -230.5,-1300.5 ; -170.5,-1280.5 -230.5,-1300.5 ; -100,0 0,0 0,-140 ; -95,3755 0,3755 ; -6.42,-1300.5 -230.5,-1300.5 ; 545.42,-1300.5 769.5,-1300.5 ; 709.5,-1320.5 769.5,-1300.5 ; 709.5,-1280.5 769.5,-1300.5 ; 769.5,-1310.5 769.5,-1290.5 ; 4370,-110 4370,0
  text "1000 (mil)" at 3.58,-1336.49 h60
  text ".Layer_Name" at 347,-1693.49 h40
M3 3D STEP Top:
  text ".Layer_Name" at 347,-1693.49 h40
M4 3D STEP Bottom:
  text ".Layer_Name" at 347,-1693.49 h40
M5 Assembly Top:
  lines w10: -522,-1765.17 6078,-1765.17 ; -522,-1561.83 6080,-1561.83 ; -522,-1358.5 -522,-1968.5 3483,-1968.5 6080,-1968.5 6080,-1358.5 -521.5,-1358.5 -521.5,-1968.5 1054,-1968.5 ; 1943,-1968.5 1943,-1358.5 ; 3210,-1561.83 3210,-1358.5 ; 4050,-1561.83 4050,-1358.5 ; 4672,-1975 4672,-1772.17
  text "COMPONENTS MARKED 'DNP' SHOULD NOT BE POPULATED." at 923.5,-1153.5 h40
  text "ASSEMBLY VARIANT:" at 923,-1269 h40
  text ".VariantName" at 1959,-1269 h40
  text "PCB VIEWED FROM TOP SIDE" at -458.5,-1490.67 h40
  text "BOARD #:" at 2018,-1490.67 h40
  text ".PRJ_Number" at 2563.5,-1490.67 h40
  text "REV:" at 3408,-1490.67 h40
  text ".PCB_Rev" at 3699.5,-1490.67 h40
  text "SVN REV:" at 4246,-1490.67 h40
  text ".VersionControl_RevNumber" at 4752,-1490.67 h40
  text "IGNORE ->" at -458.5,-1693.49 h40
  text "PLOT NAME =" at -458.5,-1899.33 h40
  text ".plot_File_Name" at 347,-1899.33 h40
  text "GENERATED    :" at 2020,-1899.33 h40
  text ".Print_Date" at 2889.5,-1899.33 h40
  text ".Print_Time" at 3618.5,-1899.33 h40
  text "TEXAS INSTRUMENTS" at 4883,-1899.33 h40
M6 Assembly Bottom:
  lines w10: -522.5,-1562.33 6079.5,-1562.33 ; -520.5,-1765.67 6079.5,-1765.67 ; 885.5,-1975.5 885.5,-1772.67 ; 1507.5,-1562.33 1507.5,-1359 ; 2347.5,-1562.33 2347.5,-1359 ; 3614.5,-1969 3614.5,-1359 ; 4503.5,-1969 6079,-1969 6079,-1359 -522.5,-1359 -522.5,-1969 2074.5,-1969 6079.5,-1969 6079.5,-1359
  text "COMPONENTS MARKED 'DNP' SHOULD NOT BE POPULATED." at 5872,-1153 h40
  text ".VariantName" at 4828,-1269 h40
  text "ASSEMBLY VARIANT:" at 5867,-1269 h40
  text ".VersionControl_RevNumber" at 805.5,-1491.17 h40
  text "SVN REV:" at 1311.5,-1491.17 h40
  text ".PCB_Rev" at 1858,-1491.17 h40
  text "REV:" at 2149.5,-1491.17 h40
  text ".PRJ_Number" at 2994,-1491.17 h40
  text "BOARD #:" at 3539.5,-1491.17 h40
  text "PCB VIEWED FROM BOTTOM SIDE" at 6016,-1491.17 h40
  text "IGNORE ->" at 2317.85,-1693.49 h40
  text "TEXAS INSTRUMENTS" at 674.5,-1899.83 h40
  text ".Print_Time" at 1939,-1899.83 h40
  text ".Print_Date" at 2668,-1899.83 h40
  text "GENERATED    :" at 3537.5,-1899.83 h40
  text ".plot_File_Name" at 5210.5,-1899.83 h40
  text "PLOT NAME =" at 6016,-1899.83 h40
M9 Title Sheet:
  drawing of 57 lines, arcs and shapes, not listed
  text "1" at 509.84,7201.5 h40
  text "2" at 3005.5,7201.5 h40
  text "3" at 5494.84,7201.5 h40
  text "4" at 8001.51,7201.5 h40
  text "5" at 10500.5,7201.5 h40
  text "6" at 13005.5,7201.5 h40
  text "A" at -646.5,6058.5 h40
  text "A" at 14153.5,6058.5 h40
  text "B" at -646.5,3678.5 h40
  text "B" at 14153.5,3678.5 h40
  text "C" at -646.5,1303.5 h40
  text "C" at 14153.5,1303.5 h40
  text "PROJECT TITLE:" at 11113.5,-557.5 h40
  text ".PRJ_Title" at 11163.5,-690.83 h40
  text "DESIGNED FOR:" at 11113.5,-858.5 h40
  text ".PRJ_Customer" at 11163.5,-998.5 h40
  text "D" at -646.5,-1066.5 h40
  text "D" at 14153.5,-1066.5 h40
  text "FILE NAME:" at 11113.5,-1158.5 h40
  text ".PCB_File_Name_No_Path" at 11163.5,-1278.5 h40
  text "Texas Instruments (TI) and/or its licensors do not warrant the accuracy or completeness of this specification" at 6144,-1440.34 h40
  text "ENGINEER:" at 11113.5,-1448.5 h40
  text "LAYOUT BY:" at 12618.5,-1448.5 h40
  text "or any information contained therein. TI and/or its licensors do not warrant that this design will meet" at 6099.01,-1553 h40
  text ".PRJ_Engineer" at 11163.5,-1603.49 h40
  text ".PCB_Layout" at 12669,-1603.49 h40
  text "the specifications, will be suitable for your application or fit for any particular purpose, or will operate in" at 6099.01,-1665.67 h40
  text ".Layer_Name" at 347,-1693.49 h40
  text "ALTIUM DESIGNER VERSION:" at 12618.5,-1758.5 h40
  text "an implementation. TI and/or its licensors do not warrant that the design is production worthy. You should" at 6099.01,-1778.33 h40
  text "completely validate and test your design implementation to confirm the system functionality for your application." at 6144,-1891 h40
  text ".print_Scale" at 11163.5,-1891.83 h40
  text ".Application_BuildNumber" at 12669,-1891.83 h40
  text "1" at 509.84,-2098.5 h40
  text "2" at 3005.5,-2098.5 h40
  text "3" at 5494.84,-2098.5 h40
  text "4" at 8001.51,-2098.5 h40
  text "5" at 10500.5,-2098.5 h40
  text "6" at 13005.5,-2098.5 h40
M10 Fab Notes:
  drawing of 212 lines, arcs and shapes, not listed
  text "DESIGN INFORMATION" at 12151.02,5975 h40
  text "(REFER ALSO ARRAY/PANEL PROFILING INFORMATION)" at 11789.46,5813.29 h40
  text "BOARD SIZE" at 11103.46,5809 h40
  text "3450MIL" at 11565.78,5681.18 h40
  text "X" at 12071.46,5681.18 h40
  text "4950MIL" at 12302.78,5681.18 h40
  text "Number of Layers :" at 11506.46,5484 h40
  text "2" at 12601.27,5474 h40
  text "MIN. TRACK WIDTH:" at 11506.46,5345 h40
  text "8" at 12602.7,5345 h40
  text "MIL" at 12757.46,5345 h40
  text "MIN. CLEARANCE:" at 11506.46,5213 h40
  text "8" at 12602.7,5213 h40
  text "MIL" at 12757.46,5213 h40
  text "MIN. VIA PAD SIZE:" at 11506.46,5081 h40
  text "24" at 12572.71,5081 h40
  text "MIL" at 12757.46,5081 h40
  text "0.05mm (2MIL)" at 12201.46,4939.29 h40
  text "MINIMUM ANNULAR RING" at 11177.23,4935.01 h40
  text "EXTERNAL" at 12909.46,4935.01 h40
  text "PER" at 11377.23,4817 h40
  text "IPC-D-275 CLASS 2 LEVEL C" at 11597.23,4817 h40
  text "MIL, HOLES" at 13085.46,4704.71 h40
  text "+/-" at 12693,4704 h40
  text "+/-" at 13547,4704 h40
  text "REGISTRATION TOLERANCES:" at 11177.23,4699 h40
  text "METAL" at 12377,4699 h40
  text "5" at 12953.2,4699 h40
  text "3" at 13786.2,4699 h40
  text "MIL" at 13902.46,4699 h40
  text "MATERIAL:" at 11102.46,4489.54 h40
  text "FR-4 High Tg" at 12088.9,4349.21 h40
  text "FR-408" at 11523.46,4340.64 h40
  text "X" at 11935.46,4340.64 h40
  text "OTHER" at 13011.46,4340.64 h40
  text "62 MIL (1.6mm) +/-10%" at 11843.56,4177.92 h40
  text "THICKNESS:" at 11177.23,4173.64 h40
  text "X" at 11715.4,4173.64 h40
  text "OTHER" at 13128.46,4173.64 h40
  text "TOLERANCE:" at 11177.23,4015.64 h40
  text "X" at 12016.53,4015.64 h40
  text "ANSI IPC-6012 TYPE 3 CLASS 2" at 12203.48,4015.64 h40
  text "OTHER +/-" at 12203.46,3859.64 h40
  text "BOW & TWIST:" at 11177.23,3702.64 h40
  text "X" at 12016.53,3702.64 h40
  text "ANSI IPC-6012 TYPE 3 CLASS 2" at 12203.48,3702.64 h40
  text "OTHER +/-" at 12203.46,3544.13 h40
  text "COPPER THICKNESS (FINISHED):" at 11102.46,3408.64 h40
  text "1.4MIL (1oz)" at 11982.46,3255.92 h40
  text "2MIL (1.4oz)" at 12749.46,3255.92 h40
  text "2.8MIL (2oz)" at 13476.46,3255.92 h40
  text "OUTER:" at 11459.46,3251.64 h40
  text "X" at 11854,3251 h40
  text "1.4MIL (1oz)" at 11982.46,3098.92 h40
  text "2.8MIL (2oz)" at 12749.46,3098.92 h40
  text "N/A" at 13476,3099.29 h40
  text "INNER SIGNAL:" at 11170.38,3094.64 h40
  text "X" at 11855.42,3094.64 h40
  text "DRILLING:" at 11102.46,2955.64 h40
  text "REFERENCE:" at 11177.23,2838.64 h40
  text "X" at 11825.46,2838.64 h40
  text "AS SHOWN" at 12012.46,2838.64 h40
  text "X" at 12726.46,2838.64 h40
  text "NC_DRILL FILES" at 12863.46,2838.64 h40
  text "PTH MIN COPPER THICKNESS:" at 11177.23,2680.64 h40
  text "X" at 12527.46,2680.64 h40
  text "1MIL" at 12664.46,2680.64 h40
  text "OTHER" at 13161.46,2680.64 h40
  text "BOARD FINISH:" at 11102.46,2521.64 h40
  text "SILKSCREEN:" at 11257.68,2403.64 h40
  text "X" at 12206.46,2403.64 h40
  text "TOP" at 12332.46,2403.64 h40
  text "X" at 12716.46,2403.64 h40
  text "BOTTOM" at 12843.46,2403.64 h40
  text "SILKSCREEN COLOR:" at 11257.68,2236.64 h40
  text "X" at 12205.42,2236.64 h40
  text "WHITE" at 12332.46,2236.64 h40
  text "OTHER" at 12843.46,2236.64 h40
  text "SOLDER RESIST COLOR:" at 11257.68,2066.64 h40
  text "X" at 11825.42,1907.44 h40
  text "GREEN" at 11952.46,1907.44 h40
  text "BLUE" at 12543.46,1907.44 h40
  text "OTHER" at 13081.46,1907.44 h40
  text "IMMERSION GOLD (ENIG)" at 12163.46,1718.92 h40
  text "ENEPIG" at 13501,1715.64 h40
  text "SURFACE FINISH:" at 11102.46,1714.64 h40
  text "X" at 11976.51,1714.64 h40
  text "IMM. TIN/SILVER OR EQUIV" at 11432,1557.64 h40
  text "OTHER" at 12863.46,1557.64 h40
  text "ARRAY/PANEL:" at 11102.46,1378.64 h40
  text "CUT AND TRIM PER MECH LAYER 1" at 12163.46,1374.35 h40
  text "N.C. ROUTE" at 12163.46,1222.64 h40
  text "X" at 12842.46,1222.64 h40
  text "V. SCORE" at 13029.46,1222.64 h40
  text "CERTIFICATION:" at 11102.46,1085.64 h40
  text "MATERIALS AND WORKMANSHIP FOR ALL PCBS" at 11827.46,1085.64 h40
  text "TO MEET OR EXCEED THE REQUIREMENTS OF:" at 11827.46,987.64 h40
  text "X" at 11453.96,851.14 h40
  text "ANSI IPC-A-600F CLASS ->" at 11592.96,851.14 h40
  text "X" at 13232.02,851.14 h40
  text "2" at 13350.96,851.14 h40
  text "1" at 13035.96,849.64 h40
  text "3" at 13704.96,849.64 h40
  text "X" at 11456.02,691.64 h40
  text "UL 94V-0" at 11592.96,691.64 h40
  text "X" at 12268.02,691.64 h40
  text "RoHS" at 12404.96,691.64 h40
  text "OTHER" at 13049.36,691.64 h40
  text "PER ORDER" at 13446.42,691.64 h40
  text "ADDITIONAL REQUIREMENTS:" at 11102.46,550.64 h40
  text "MICROSECTION:" at 11177.23,435.64 h40
  text "YES" at 12082.96,435.64 h40
  text "REQUIRED" at 12944.46,279.5 h40
  text "BARE BOARD ELEC. TEST:" at 11177.23,276.64 h40
  text "NONE" at 12482.96,276.64 h40
  text "X" at 12817.46,276.64 h40
  text "PER ORDER" at 13536.46,276.64 h40
  text "MANUFACTURER'S UL:" at 11177.23,119.64 h40
  text "RAIL" at 12342.96,115.35 h40
  text "METAL" at 12834.77,115.35 h40
  text "X" at 13210,115 h40
  text "SILK" at 13346.46,115.35 h40
  text ".Layer_Name" at 347,-1693.49 h40
M11 Gerber Information:
  lines w10: -522,-1765.17 6078,-1765.17 ; -522,-1561.83 6080,-1561.83 ; -522,-1358.5 -522,-1968.5 3483,-1968.5 6080,-1968.5 6080,-1358.5 -521.5,-1358.5 -521.5,-1968.5 1054,-1968.5 ; 1943,-1968.5 1943,-1358.5 ; 3210,-1561.83 3210,-1358.5 ; 4050,-1561.83 4050,-1358.5 ; 4672,-1975 4672,-1772.17
  text "ALL ARTWORK VIEWED FROM TOP SIDE" at -458.5,-1490.67 h40
  text "BOARD #:" at 2018,-1490.67 h40
  text ".PRJ_Number" at 2563.5,-1490.67 h40
  text "REV:" at 3408,-1490.67 h40
  text ".PCB_Rev" at 3699.5,-1490.67 h40
  text "SVN REV:" at 4246,-1490.67 h40
  text ".VersionControl_RevNumber" at 4752,-1490.67 h40
  text "LAYER NAME =" at -458.5,-1693.49 h40
  text "PLOT NAME =" at -458.5,-1899.33 h40
  text ".plot_File_Name" at 347,-1899.33 h40
  text "GENERATED    :" at 2020,-1899.33 h40
  text ".Print_Date" at 2889.5,-1899.33 h40
  text ".Print_Time" at 3618.5,-1899.33 h40
  text "TEXAS INSTRUMENTS" at 4883,-1899.33 h40
M12 Stackup:
  lines w6: 11130,6625 13680,6625 ; 11130,6729.4 13680,6729.4 ; 11070,6140 ccw(c11104,6140) 11104,6106 13706,6106 ccw(c13706,6140) 13740,6140 13740,6846 ccw(c13706,6846) 13706,6880 11104,6880 ccw(c11104,6846) 11070,6846 11070,6140
  text "The Stackup Legend below this is static." at 11375.5,7039.5 h40
  text "If you change the stackup, update the Legend." at 11385.5,6949.5 h40
  text "Layer Stack Up Detail for: Ref_Design.PcbDoc" at 11130,6762.1 h40
  text "Layer" at 11130,6690.4 h40
  text "Gerber" at 12025.81,6690.4 h40
  text "Copper" at 12589.33,6690.4 h40
  text "Dielectric" at 13192.04,6690.4 h40
  text "Name" at 11130,6642.4 h40
  text "Document" at 12025.81,6642.4 h40
  text "Thickness" at 12589.33,6642.4 h40
  text "Material" at 13192.04,6642.4 h40
  text "Top Solder Mask" at 11130,6549.44 h40
  text "(.GTS)" at 12025.81,6549.44 h40
  text "Solder Resist" at 13192.04,6549.44 h40
  text "Top Layer" at 11130,6452.69 h40
  text "(.GTL)" at 12025.81,6452.69 h40
  text "1.4mil" at 12589.33,6452.69 h40
  text "FR-4" at 13192.04,6404.31 h40
  text "Bottom Layer" at 11130,6355.94 h40
  text "(.GBL)" at 12025.81,6355.94 h40
  text "1.4mil" at 12589.33,6355.94 h40
  text "Bottom Solder Mask" at 11130,6259.19 h40
  text "(.GBS)" at 12025.81,6259.19 h40
  text "Solder Resist" at 13192.04,6259.19 h40
  text ".Layer_Name" at 347,-1693.49 h40
M13 Component Bodies Top:
  text ".Layer_Name" at 347,-1693.49 h40
M14 Component Bodies Bottom:
  text ".Layer_Name" at 347,-1693.49 h40
M15 Courtyards Top:
  text ".Layer_Name" at 347,-1693.49 h40
M16 Courtyards Bottom:
  text ".Layer_Name" at 347,-1693.49 h40
Drill Drawing:
  text ".legend" at 4892.5,-109.5 h40
  text "Drill Table" at 4917.5,-294.5 h40
  text ".Layer_Name" at 347,-1693.49 h40

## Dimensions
-100,0 to -150,3750 on M2 Board Dimensions
0,-140 to 4370,0 on M2 Board Dimensions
